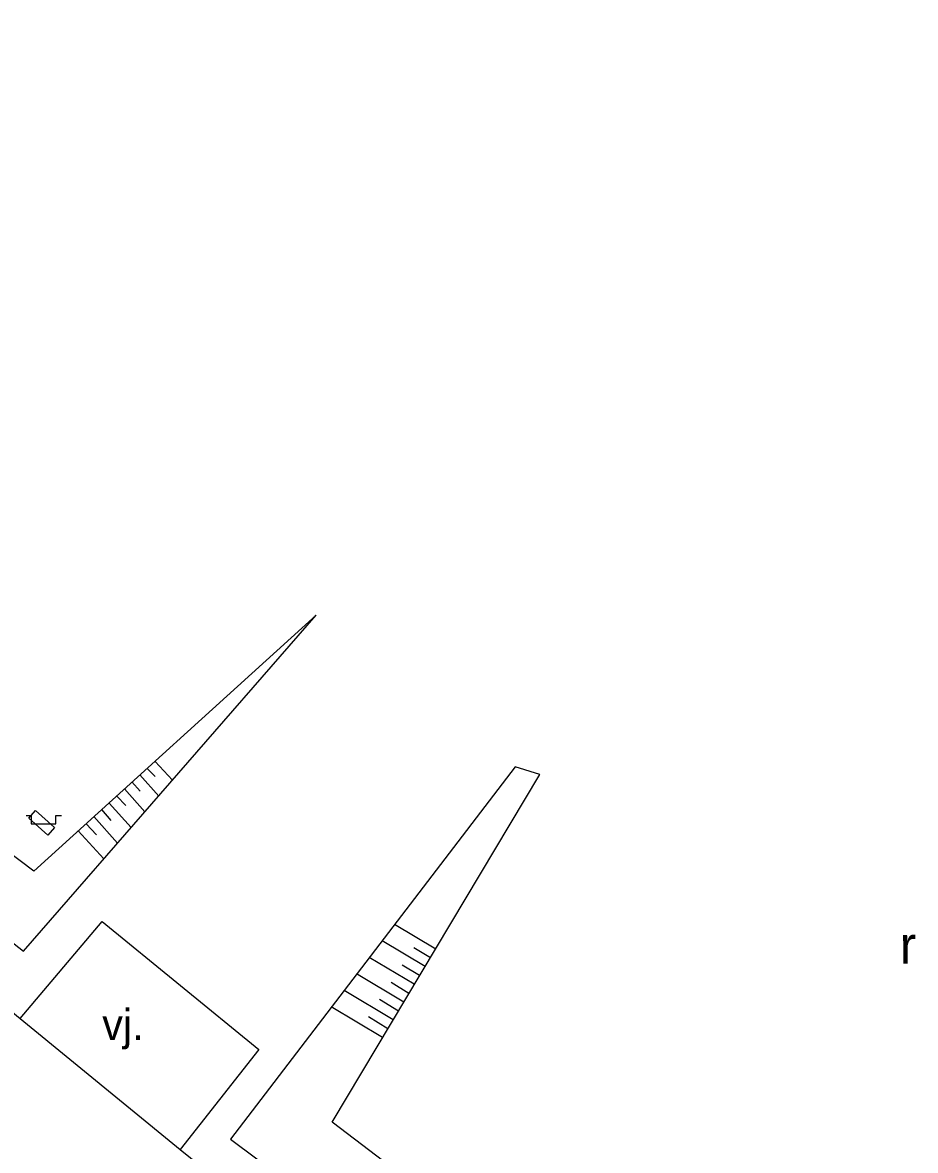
# Model space of a CAD drawing. Extents: x -836568 to -836015, y -1070547 to -1070212.
# Drawn here: x -836460.84 to -836439.21, y -1070349.39 to -1070322.06 of the extents above; entities that cross this region are included whole.
import ezdxf

# ---------------------------------------------------------------- set-up
doc = ezdxf.new("R2010")
doc.units = 0
for name, color, linetype in [('BodPole_mer', 7, 'Continuous'), ('Doprava_hranice', 7, 'Continuous'), ('Doprava_kody', 7, 'Continuous'), ('OstPloch_kody', 7, 'Continuous'), ('PovrZnIS_hranice', 7, 'Continuous'), ('PovrZnIS_kody', 7, 'Continuous'), ('Vyskopis_linie', 7, 'Continuous')]:
    doc.layers.add(name, color=color, linetype=linetype)

msp = doc.modelspace()

# ---------------------------------------------------------------- linework, layer by layer
at = {"layer": 'BodPole_mer'}
for p, q in [((-836453.73, -1070336.42), (-836453.73, -1070336.42)), ((-836448.91, -1070340.09), (-836448.91, -1070340.09)), ((-836448.31, -1070340.28), (-836448.31, -1070340.28)), ((-836460.69, -1070341.34), (-836460.69, -1070341.34)), ((-836460.69, -1070341.34), (-836460.69, -1070341.34)), ((-836460.53, -1070341.15), (-836460.53, -1070341.15)), ((-836460.53, -1070341.15), (-836460.53, -1070341.15)), ((-836460.07, -1070341.56), (-836460.07, -1070341.56)), ((-836460.07, -1070341.56), (-836460.07, -1070341.56)), ((-836460.23, -1070341.75), (-836460.23, -1070341.75)), ((-836460.23, -1070341.75), (-836460.23, -1070341.75)), ((-836460.57, -1070342.62), (-836460.57, -1070342.62)), ((-836458.91, -1070343.84), (-836458.91, -1070343.84)), ((-836460.82, -1070344.56), (-836460.82, -1070344.56)), ((-836455.12, -1070346.94), (-836455.12, -1070346.94)), ((-836453.34, -1070348.7), (-836453.34, -1070348.7)), ((-836455.8, -1070349.11), (-836455.8, -1070349.11)), ((-836457.02, -1070349.36), (-836457.02, -1070349.36))]:
    msp.add_line(p, q, dxfattribs=at)
at = {"layer": 'Doprava_hranice'}
for points in [[(-836486.04, -1070295.25), (-836491.51, -1070301.7), (-836496.11, -1070306.84), (-836497.41, -1070308.37), (-836498.02, -1070309.18), (-836498.47, -1070310.1), (-836498.73, -1070311.08), (-836498.85, -1070312.07), (-836498.78, -1070313.12), (-836498.51, -1070314.1), (-836498.1, -1070315.03), (-836497.52, -1070315.85), (-836497.01, -1070316.45), (-836496.48, -1070317), (-836489.02, -1070323.12), (-836476.76, -1070333.19), (-836472.89, -1070336.35), (-836460.9, -1070346.19), (-836457.02, -1070349.36), (-836453.9, -1070351.88), (-836451.54, -1070353.74), (-836449.19, -1070355.59), (-836447.61, -1070356.83), (-836445.19, -1070358.65)], [(-836460.9, -1070346.19), (-836458.91, -1070343.84), (-836455.12, -1070346.94), (-836457.02, -1070349.36)]]:
    msp.add_lwpolyline(points, dxfattribs=at)
at = {"layer": 'PovrZnIS_hranice'}
msp.add_line((-836460.69, -1070341.34), (-836460.23, -1070341.75), dxfattribs=at)
msp.add_line((-836460.69, -1070341.34), (-836460.23, -1070341.75), dxfattribs=at)
msp.add_lwpolyline([(-836460.69, -1070341.34), (-836460.53, -1070341.15), (-836460.07, -1070341.56), (-836460.23, -1070341.75)], dxfattribs=at)
msp.add_lwpolyline([(-836460.69, -1070341.34), (-836460.53, -1070341.15), (-836460.07, -1070341.56), (-836460.23, -1070341.75)], dxfattribs=at)
at = {"layer": 'PovrZnIS_kody'}
for p, q in [((-836460.751, -1070341.27), (-836460.63, -1070341.27)), ((-836460.751, -1070341.27), (-836460.63, -1070341.27)), ((-836460.63, -1070341.27), (-836460.63, -1070341.47)), ((-836460.63, -1070341.27), (-836460.63, -1070341.47)), ((-836460.03, -1070341.47), (-836460.03, -1070341.27)), ((-836460.03, -1070341.27), (-836459.896, -1070341.27)), ((-836460.03, -1070341.47), (-836460.03, -1070341.27)), ((-836460.03, -1070341.27), (-836459.896, -1070341.27)), ((-836460.63, -1070341.47), (-836460.03, -1070341.47)), ((-836460.63, -1070341.47), (-836460.03, -1070341.47))]:
    msp.add_line(p, q, dxfattribs=at)
at = {"layer": 'Vyskopis_linie'}
for p, q in [((-836457.63, -1070339.96), (-836457.21, -1070340.42)), ((-836457.82, -1070340.13), (-836457.63, -1070340.33)), ((-836458.19, -1070340.46), (-836457.99, -1070340.68)), ((-836458, -1070340.29), (-836457.54, -1070340.8)), ((-836458.56, -1070340.8), (-836458.34, -1070341.03)), ((-836458.37, -1070340.63), (-836457.88, -1070341.18)), ((-836458.74, -1070340.97), (-836458.21, -1070341.56)), ((-836459.11, -1070341.3), (-836458.54, -1070341.94)), ((-836458.93, -1070341.13), (-836458.7, -1070341.39)), ((-836459.3, -1070341.47), (-836459.05, -1070341.74)), ((-836459.49, -1070341.64), (-836458.87, -1070342.32)), ((-836450.83, -1070344.51), (-836451.83, -1070343.91)), ((-836451.09, -1070344.93), (-836452.13, -1070344.31)), ((-836450.96, -1070344.72), (-836451.36, -1070344.48)), ((-836451.35, -1070345.36), (-836452.44, -1070344.71)), ((-836451.22, -1070345.15), (-836451.64, -1070344.9)), ((-836451.6, -1070345.79), (-836452.75, -1070345.11)), ((-836451.48, -1070345.58), (-836451.91, -1070345.32)), ((-836451.86, -1070346.22), (-836453.05, -1070345.51)), ((-836452.12, -1070346.65), (-836453.36, -1070345.91)), ((-836451.73, -1070346.01), (-836452.19, -1070345.73)), ((-836451.99, -1070346.44), (-836452.46, -1070346.15))]:
    msp.add_line(p, q, dxfattribs=at)
for points in [[(-836462.64, -1070326.86), (-836468.3, -1070331.68), (-836471.46, -1070336.19), (-836460.82, -1070344.56), (-836453.73, -1070336.42)], [(-836453.73, -1070336.42), (-836460.57, -1070342.62), (-836469.27, -1070336.05), (-836462.64, -1070326.86)], [(-836448.31, -1070340.28), (-836448.91, -1070340.09), (-836455.8, -1070349.11), (-836445.09, -1070357.11), (-836439.64, -1070349.82)], [(-836439.64, -1070349.82), (-836445.29, -1070354.83), (-836453.34, -1070348.7), (-836448.31, -1070340.28)]]:
    msp.add_lwpolyline(points, dxfattribs=at)

# ---------------------------------------------------------------- texts
at = {"layer": 'Doprava_kody'}
msp.add_text('vj.', height=0.75, dxfattribs=at).set_placement((-836458.91, -1070346.71))
at = {"layer": 'OstPloch_kody'}
msp.add_text('r', height=0.9, dxfattribs=at).set_placement((-836439.59, -1070344.86))

doc.saveas('drawing.dxf')
